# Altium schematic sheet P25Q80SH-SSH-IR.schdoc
size 127 x 101 mm
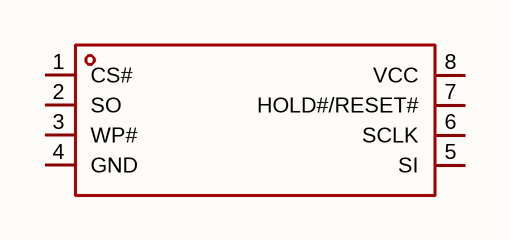
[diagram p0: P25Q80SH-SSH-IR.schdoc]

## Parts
U?  p25q80sh-ssh-ir  [SOP-8_L4.9-W3.9-P1.27-LS6.0-BL]  (value not drawn)

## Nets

Not connected (* = marked no-connect by the designer): U? 1(CS#) 2(SO) 3(WP#) 4(GND) 5(SI) 6(SCLK) 7(HOLD#/RESET#) 8(VCC)

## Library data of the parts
U? = p25q80sh-ssh-ir: 接口类型:SPI;存储容量:8Mbit;时钟频率(fc):120MHz;; Manufacturer: PUYA(普冉); AddInBom: yes; ModelId: 75c24a7891ee4dd6bdac16a7163ff87e; ModelName: SOP-8_L4.9-W3.9-P1.27-LS6.0-BL-1; ModelTransform: 192.913,236.22,0,0,0,0,-0.393,2.749,0; Interface: SPI; Memory Size: 8Mbit; Clock Frequency: 120MHz; Voltage - Supply: 2.3V~3.6V; Standby Supply Current: 10uA; Program / Erase Cycles: 100000次; Page Programming Time (Tpp): 1.5ms; Block Erase Time(tBE): 16ms; Data Retention - TDR (Year): 20年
